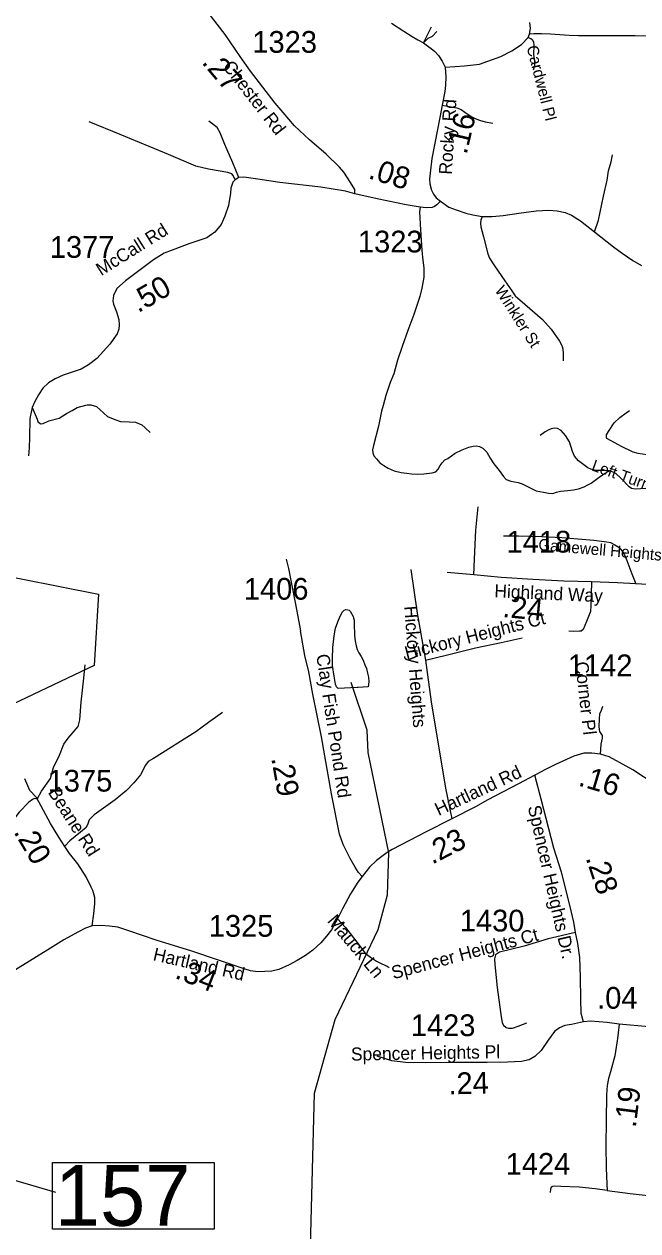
# Model space of a CAD drawing. Extents: x 1159738 to 1321356, y 736314 to 882035.
# Drawn here: x 1223604 to 1227136, y 777846 to 784785 of the extents above; entities that cross this region are included whole.
import ezdxf

# ---------------------------------------------------------------- set-up
doc = ezdxf.new("R2010")
doc.units = 0
for name, color, linetype in [('Exist Boundary Political City Limit New InsideOut', 7, 'Continuous'), ('Exist Hydrographic Creek Single Shore', 7, 'Continuous'), ('Exist Hydrographic Misc Water Feature', 7, 'Continuous'), ('Exist Road Non-System Type 51', 7, 'Continuous'), ('Exist Road Non-System Type 51 Label', 7, 'Continuous'), ('Exist Road Secondary Mileage Hundredths English Label', 7, 'Continuous'), ('Exist Road Secondary Structure Standard Bridge Number Label', 7, 'Continuous'), ('Exist Road Secondary Type 41 Attributed', 7, 'Continuous'), ('Exist Road Secondary Type 51 Attributed', 7, 'Continuous'), ('Exist Road Secondary Type 51 Label', 7, 'Continuous'), ('Exist Road Secondary Type 51 Number Label', 7, 'Continuous')]:
    doc.layers.add(name, color=color, linetype=linetype)

msp = doc.modelspace()

# ---------------------------------------------------------------- linework, layer by layer
at = {"layer": 'Exist Boundary Political City Limit New InsideOut'}
msp.add_lwpolyline([(1223353.7, 781642.3), (1224031.6, 781507.2), (1224008.1, 781097.1), (1223340.4, 780779.9)], dxfattribs=at)
at = {"layer": 'Exist Hydrographic Creek Single Shore'}
msp.add_lwpolyline([(1224472, 776290), (1224764, 776635.4), (1225252, 777754.8), (1225275, 778637.3), (1225394, 779061.7), (1225641, 779578.6), (1225696, 779777.8), (1225702, 780020.5), (1225583.9, 780597.4), (1225579, 780725.5), (1225486, 780999.8)], dxfattribs=at)
at = {"layer": 'Exist Hydrographic Misc Water Feature'}
msp.add_lwpolyline([(1225519.9, 780970.4), (1225411.7, 780965.2), (1225402, 780975.2), (1225396.4, 780990.1), (1225387.6, 781036.2), (1225379, 781096.3), (1225378.1, 781136.5), (1225379.8, 781200.5), (1225387.5, 781268.5), (1225396.7, 781311.8), (1225409.6, 781347.6), (1225422.4, 781381), (1225437.1, 781405.4), (1225445.3, 781415), (1225455.4, 781418.1), (1225467.4, 781417.9), (1225475.4, 781416.1), (1225481.2, 781410.2), (1225498.4, 781379.5), (1225500.2, 781371.3), (1225503.8, 781357.2), (1225503.3, 781337.5), (1225505.6, 781271), (1225508.8, 781237.3), (1225514.2, 781211), (1225521.5, 781188.7), (1225531.1, 781170.4), (1225544.4, 781148), (1225556, 781128.1), (1225565.3, 781101.6), (1225574.8, 781079.3), (1225580.1, 781052.9), (1225585.4, 781029), (1225586.8, 781002.7), (1225584.1, 780974.8), (1225526, 780970.3), (1225519.9, 780970.4)], dxfattribs=at)
at = {"layer": 'Exist Road Non-System Type 51'}
for points in [[(1225901.8, 784678.2), (1225948, 784770.7)], [(1225901.8, 784678.2), (1225929.1, 784705.6), (1225954.3, 784716.1), (1225979.5, 784743.4)], [(1226504, 784708.7), (1226520.6, 784703.1), (1226527.8, 784696.8), (1226534.9, 784684.1), (1226538.1, 784664.2), (1226534.9, 784611.1), (1226540.4, 784573), (1226541.2, 784545.3), (1226534.1, 784520.7)], [(1227208.2, 784716), (1227120.3, 784717.8), (1227023.2, 784717.8), (1226923.5, 784717.8), (1226793.8, 784718.7), (1226739.8, 784719.5), (1226633.7, 784726.8), (1226582.1, 784729.5), (1226537.6, 784730.4), (1226511.3, 784728.6)], [(1226010.3, 784318.9), (1226041.1, 784313.5), (1226093.7, 784304.4), (1226118.2, 784295.3), (1226140, 784279), (1226177.2, 784253.6), (1226198.9, 784243.6), (1226224.3, 784233.6), (1226257, 784223.7), (1226300.5, 784215.5)], [(1224818.2, 783889.8), (1224807.8, 783914.5), (1224799.6, 783924.3), (1224776.8, 783932.5), (1224665.6, 783952.1), (1224592.1, 783968.5), (1224435.3, 784035.5), (1224157.5, 784151.6), (1223979.4, 784223.6)], [(1224839.1, 783903.5), (1224804.8, 783987.3), (1224759.7, 784092.5), (1224732.9, 784161.2), (1224715.7, 784191.3), (1224666.3, 784226.7)], [(1226887, 783590.8), (1226910.1, 783657.6), (1226937.3, 783795.6), (1226959.1, 783887.2), (1226967.2, 783942.2), (1226981.7, 783993.9), (1226989, 784032.9)], [(1225882.8, 783732.3), (1225880, 783706), (1225885.5, 783602.5), (1225893.6, 783482.7), (1225896.4, 783445.5), (1225904.5, 783382.9), (1225904.5, 783329.4), (1225892.7, 783266.7), (1225881, 783218.5), (1225847.4, 783115.9), (1225812.1, 783023.4), (1225779.4, 782930.8), (1225753.1, 782852.7), (1225732.4, 782773.6), (1225709.7, 782723.7), (1225685.2, 782649.3), (1225669.8, 782592.1), (1225660.7, 782560.4), (1225643.5, 782474.2), (1225613.7, 782362), (1225609.2, 782336.6), (1225611, 782320.3), (1225617.3, 782302.2), (1225630.9, 782284.9), (1225651.8, 782263.1), (1225673.5, 782246.8), (1225699.8, 782232.3), (1225734.3, 782216.9), (1225773.3, 782206.9), (1225805, 782202.3), (1225834, 782198.7), (1225864.9, 782197.8), (1225903.9, 782198.7), (1225951.6, 782204.2), (1225973.3, 782210.5), (1225986, 782226), (1225997.8, 782247.7), (1226009.6, 782263.2), (1226025.9, 782279.5), (1226043.1, 782287.7), (1226084, 782317.6), (1226124.8, 782336.7), (1226162.9, 782352.1), (1226188.2, 782357.6), (1226207.3, 782359.4), (1226224.5, 782355.7), (1226244.5, 782347.6), (1226267.1, 782324), (1226286.2, 782289.5), (1226307.9, 782256.8), (1226337.9, 782218.7), (1226362.4, 782184.2), (1226377.8, 782166.1), (1226404.1, 782157.9), (1226447.6, 782149.7), (1226470.8, 782141), (1226511.6, 782120.1), (1226551.5, 782101.9), (1226593.2, 782093.8), (1226621.3, 782088.3), (1226645.8, 782085.6), (1226666.7, 782093.8), (1226691.2, 782100.1), (1226732.9, 782102.8), (1226764.6, 782106.5), (1226794.5, 782113.7), (1226827.2, 782124.6), (1226847.1, 782135.5), (1226866.2, 782146.4), (1226913, 782180.9), (1226943.9, 782200.8), (1226972, 782215.6)], [(1226239.9, 783679.5), (1226232.8, 783657.2), (1226230.9, 783640), (1226231.8, 783620), (1226247.3, 783561.9), (1226272.7, 783464.8), (1226282.6, 783439.4), (1226310.7, 783395), (1226369.7, 783308.7), (1226410.4, 783251.2), (1226430.3, 783222.1), (1226484.7, 783174.9), (1226586.3, 783086), (1226636, 783031.9), (1226684, 782962), (1226696.7, 782940.2), (1226701.3, 782926.6), (1226705.8, 782896.7), (1226706.7, 782849.5)], [(1223650.9, 782580.7), (1223679.5, 782513.3), (1223683.6, 782501), (1223697.8, 782486.7), (1223714.2, 782488.8), (1223746.8, 782503.1), (1223806, 782519.4), (1223848.8, 782546), (1223881.5, 782564.3), (1223910, 782580.7), (1223959, 782595), (1223967.2, 782597), (1223987.6, 782597), (1224020.2, 782586.8), (1224083.5, 782529.6), (1224126.3, 782511.3), (1224159, 782501), (1224207.9, 782499), (1224244.7, 782497), (1224281.4, 782480.6), (1224299.8, 782464.3), (1224330.4, 782437.7)], [(1227278.9, 782122.6), (1227259.6, 782249.3), (1227252.4, 782274.1), (1227242.1, 782286.8), (1227230, 782297.7), (1227214.9, 782303.7), (1227186.5, 782308.6), (1227137.5, 782315.8), (1227108.5, 782324.3), (1227042, 782355.8), (1226957.4, 782402.9), (1226955, 782408.9), (1226955.6, 782423.5), (1226966.5, 782443.4), (1226999.7, 782491.6), (1227031.8, 782522.4), (1227068.6, 782549.7), (1227088.5, 782563.3)], [(1223639.2, 782526.3), (1223636.6, 782513.3), (1223634.6, 782409.2), (1223632.6, 782347.9), (1223628.5, 782303)], [(1227181.5, 782114), (1227119.8, 782111.2), (1227099.8, 782114.9), (1227085.3, 782124), (1227039.1, 782173), (1227009.2, 782200.2), (1226992.8, 782208.3), (1226972, 782215.6), (1226947.5, 782219.2), (1226919.4, 782219.2), (1226893.1, 782219.2), (1226865.9, 782226.5), (1226847.7, 782232.8), (1226824.2, 782251.9), (1226793.3, 782273.7), (1226770.7, 782300.9), (1226758.9, 782328.1), (1226742.6, 782382.6), (1226719.9, 782418.9), (1226694.5, 782448.8), (1226673, 782459.6), (1226656.7, 782462.3), (1226637.6, 782458.7), (1226619.5, 782450.5), (1226603.2, 782441.4), (1226574.2, 782419.6)], [(1226192, 781618.5), (1226195.6, 781709.2), (1226203.7, 781875.3), (1226216.4, 782009.2)], [(1226362.1, 781842.5), (1226448.3, 781843.4), (1226582.5, 781838), (1226697.6, 781833.4), (1226882.6, 781818), (1226957, 781808), (1226977.8, 781803.5), (1227003.2, 781790.8), (1227025.9, 781777.2), (1227045.9, 781754.5), (1227059.5, 781732.7), (1227072.2, 781700), (1227101.2, 781623.8), (1227123.6, 781566.8)], [(1225112.6, 781708.1), (1225124.8, 781654.6), (1225142.1, 781566.6), (1225163.8, 781459.5), (1225185.6, 781347.4), (1225194.7, 781296.6)], [(1225829.9, 781649.2), (1225866.8, 781397.5), (1225914, 781128)], [(1226869.7, 781577.2), (1226867, 781506.4), (1226866.1, 781442), (1226862.5, 781407.5), (1226840.7, 781350.3), (1226821.7, 781304.9), (1226809, 781295), (1226800.8, 781294), (1226768.2, 781293.1), (1226738.2, 781294)], [(1225914, 781128), (1226033.3, 781157.1), (1226202.3, 781198), (1226348.3, 781228.8), (1226470.7, 781256.9)], [(1223680, 780327.8), (1223704.5, 780374.8), (1223755.5, 780446.2), (1223773.9, 780509.5), (1223808.6, 780581), (1223833, 780644.3), (1223857.5, 780679), (1223914.7, 780746.4), (1223924.9, 780785.2), (1223933, 780885.2), (1223945.3, 781007.7), (1223955.4, 781100.8)], [(1225914, 781128), (1225946.8, 780887.6), (1226029.2, 780391.5), (1226064.6, 780215.7)], [(1224745.5, 780827.4), (1224664.8, 780769.7), (1224592.8, 780714.9), (1224347.9, 780562.1), (1224317.6, 780545.5), (1224301.8, 780523.9), (1224274.4, 780467.6), (1224235.5, 780422.9), (1224193.7, 780378.3), (1224128.9, 780323.5), (1224007.8, 780238.4), (1223977.6, 780209.6), (1223970.4, 780186.5), (1223961.7, 780164.9), (1223928.6, 780137.5), (1223866.7, 780088.5), (1223837.8, 780058.2)], [(1226921.5, 780586.8), (1226925.4, 780644.3), (1226931.7, 780679.7), (1226931.7, 780693.9), (1226924.6, 780706.5), (1226916.8, 780717.5), (1226914.4, 780728.5), (1226913.6, 780745.9), (1226915.2, 780789.2), (1226917.5, 780818.3), (1226927, 780840.4), (1226934.9, 780862.4)], [(1223680, 780327.8), (1223663.8, 780332.2), (1223651.5, 780326.1), (1223631.1, 780311.8), (1223576, 780252.6), (1223516.9, 780175), (1223500.5, 780156.6), (1223514.8, 780126), (1223525, 780070.9), (1223514.8, 780023.9), (1223425.6, 779857.9), (1223363.8, 779737.9), (1223345, 779722.9), (1223324.4, 779717.3), (1223313.2, 779722.9), (1223298.2, 779741.6), (1223275.7, 779831.7)], [(1225406.6, 779640.4), (1225453.9, 779590.2), (1225526, 779496.5), (1225566.6, 779443.2), (1225597, 779419.2), (1225632.4, 779396.3), (1225662, 779382), (1225693.2, 779367.6), (1225705, 779360)], [(1226777.3, 779561.2), (1226619, 779525.1), (1226480.8, 779483.6), (1226338.8, 779447.5), (1226316.7, 779433.2), (1226311.3, 779410.9), (1226313.1, 779377.2), (1226326.9, 779245.3), (1226348, 779090.7), (1226355.8, 779042.8), (1226363, 779027.7), (1226378.1, 779015.7), (1226391.9, 779011.5), (1226414.2, 779012.1), (1226446.6, 779022.3), (1226497.2, 779041.6)], [(1226959.4, 778078.5), (1226890.5, 778086.3), (1226797.1, 778096), (1226693, 778101.1), (1226656, 778101.7), (1226644.6, 778101.1), (1226637.7, 778096.6), (1226633.2, 778085.8), (1226630.3, 778065.3)], [(1226959.4, 778078.5), (1227091.3, 778060.1), (1227228.9, 778045.2), (1227332.5, 778039.5), (1227371.7, 778029.9)]]:
    msp.add_lwpolyline(points, dxfattribs=at)
at = {"layer": 'Exist Road Secondary Structure Standard Bridge Number Label'}
msp.add_line((1222322, 778494.1), (1223785.5, 778067.2), dxfattribs=at)
msp.add_lwpolyline([(1223768.2, 778238.9), (1224697.2, 778238.9), (1224697.2, 777854.8), (1223768.2, 777854.8)], close=True, dxfattribs=at)
at = {"layer": 'Exist Road Secondary Type 41 Attributed'}
for points in [[(1225550, 779882.9), (1225527.9, 779907.1), (1225508.4, 779936.6), (1225479.6, 779986.9), (1225439.4, 780068.3), (1225418.3, 780127), (1225373.8, 780358.6), (1225315.3, 780686.5), (1225265, 780931.3), (1225242.7, 781061.4), (1225219.3, 781155.3), (1225194.7, 781296.6)], [(1226822.7, 779047.4), (1226809.2, 779094.7), (1226808.2, 779178.7), (1226805.3, 779305.1), (1226801.3, 779416.9), (1226790.6, 779497.3), (1226777.3, 779561.2), (1226768, 779620.4), (1226743.5, 779719.5), (1226695.5, 779907.8), (1226653.2, 780046.8), (1226579.8, 780328.7), (1226543.5, 780467.2)]]:
    msp.add_lwpolyline(points, dxfattribs=at)
at = {"layer": 'Exist Road Secondary Type 51 Attributed'}
for points in [[(1225507.8, 783810), (1225506.7, 783834.8), (1225482.9, 783873.8), (1225443, 783934.7), (1225418.6, 783963.7), (1225341.6, 784037.9), (1225246.6, 784120.6), (1225159.1, 784201), (1225095, 784276.6), (1225049.4, 784330.8), (1224907.2, 784514.1), (1224847.3, 784599.7), (1224761.8, 784726.6), (1224682, 784826.5), (1224645.7, 784884.1)], [(1225718.5, 784791.5), (1225788.8, 784744.9), (1225836.3, 784714.5), (1225869.6, 784694.5), (1225901.8, 784678.2), (1225932.1, 784654.9), (1225947.3, 784645.4), (1225968.2, 784628.3), (1225989.1, 784605.5), (1226009.2, 784572.3), (1226027.1, 784537.5)], [(1226027.1, 784537.5), (1226139, 784545.1), (1226224.5, 784555.3), (1226346.8, 784599.6), (1226410.1, 784631.3), (1226467.1, 784667.5), (1226504, 784708.7), (1226511.3, 784728.6), (1226517.1, 784760.5), (1226514.6, 784794.7)], [(1226027.1, 784537.5), (1226030.9, 784483.3), (1226028.3, 784435.1), (1226025.2, 784397.7), (1226010.3, 784318.9), (1225996.7, 784249.1), (1225967.6, 784101.2), (1225950.5, 784013), (1225940.3, 783928.1), (1225937.2, 783893.2), (1225939.7, 783866.6), (1225949.2, 783831.1), (1225960, 783807), (1225975.2, 783786.7), (1225999.3, 783766.5)], [(1225507.8, 783810), (1225453.5, 783824.3), (1225312.3, 783846.9), (1225075.7, 783874), (1224948.1, 783893.2), (1224869, 783904.5), (1224839.1, 783903.5), (1224818.2, 783889.8), (1224805.8, 783876.3), (1224793.3, 783842.4), (1224792.2, 783814.1), (1224779.8, 783742.9), (1224759.5, 783681.9), (1224737.1, 783632.5), (1224702.1, 783589.6), (1224654.6, 783556.8), (1224558.6, 783524), (1224410.7, 783467.5), (1224348.8, 783430.6), (1224188.4, 783309.7), (1224137.5, 783264.5), (1224118.4, 783224.3), (1224115, 783193.7), (1224118.4, 783174.5), (1224136.5, 783130.5), (1224150, 783087.5), (1224151.1, 783057), (1224148.9, 783031), (1224139.9, 783003.9), (1224098.3, 782945.5), (1224022.7, 782863), (1223975.2, 782825.7), (1223932.3, 782801.9), (1223829.5, 782765.8), (1223783.2, 782745.4), (1223744.8, 782721.7), (1223712.1, 782692.3), (1223686.1, 782653.9), (1223663.2, 782611.3), (1223650.9, 782580.7), (1223639.2, 782526.3)], [(1225999.3, 783766.5), (1225978.8, 783745.4), (1225964.9, 783735.9), (1225951.6, 783730.2), (1225918, 783728.3), (1225882.8, 783732.3), (1225801.8, 783745.9), (1225635.8, 783780.2), (1225507.8, 783810)], [(1225999.3, 783766.5), (1226048, 783733.2), (1226089.8, 783717), (1226145.2, 783698.2), (1226187, 783688), (1226239.9, 783679.5), (1226297.9, 783678.6), (1226361, 783685.4), (1226450.6, 783697.4), (1226551.3, 783711.9), (1226622.9, 783715.3), (1226672.1, 783711.2), (1226717.3, 783701.8), (1226754.8, 783687.2), (1226806, 783654.8), (1226887, 783590.8), (1226995.9, 783504), (1227046.3, 783468.2), (1227106, 783425.5), (1227156.3, 783397.3)], [(1227308.7, 781549), (1227219.7, 781561.4), (1227123.6, 781566.8), (1227018.1, 781572.7), (1226869.7, 781577.2), (1226710, 781582.8), (1226530.8, 781590.7), (1226349.5, 781603.1), (1226192, 781618.5), (1226038.8, 781631)], [(1227235.1, 780411.9), (1227106, 780497.3), (1227030.8, 780538.5), (1226969.9, 780572.5), (1226921.5, 780586.8), (1226871.4, 780592.2), (1226824.8, 780592.2), (1226767.3, 780575.4), (1226661.8, 780527.7), (1226604.8, 780498), (1226543.5, 780467.2)], [(1226543.5, 780467.2), (1226448.7, 780416.2), (1226269.4, 780322.9), (1226204.9, 780286.6), (1226064.6, 780215.7), (1225918.5, 780140.7), (1225722.7, 780038.6), (1225693, 780021.4), (1225662, 779999), (1225631.8, 779976.2), (1225592.3, 779937.3), (1225550, 779882.9)], [(1223996.3, 779600.3), (1224005.2, 779668.8), (1224010.5, 779727.8), (1224010.5, 779762.6), (1223998.9, 779802.6), (1223990.4, 779822.6), (1223960.4, 779880.7), (1223912.9, 779955.7), (1223865.8, 780016.4), (1223837.6, 780056.3), (1223803.6, 780109), (1223755.6, 780187.6), (1223676.2, 780337.6), (1223636.1, 780377.6), (1223607.9, 780444.7)], [(1225550, 779882.9), (1225524.6, 779851.5), (1225483, 779783.7), (1225436, 779697.8), (1225406.6, 779640.4), (1225372.4, 779577.3), (1225344.9, 779541.1), (1225312.1, 779501.5), (1225264.6, 779459.4), (1225223, 779428.6), (1225175.4, 779400.4), (1225128.4, 779374.9), (1225069.6, 779348.9), (1225028.7, 779338.2), (1224948.2, 779335.6), (1224906.2, 779341.8), (1224875.8, 779350.7), (1224569.4, 779454.5), (1224363.8, 779517.9), (1224205.8, 779571.8), (1224142.8, 779591.5), (1224096.1, 779597.7), (1224044.3, 779601.7), (1223996.3, 779600.3)], [(1223996.3, 779600.3), (1223957.8, 779585.6), (1223912.5, 779563.4), (1223833.5, 779519.2), (1223740.7, 779462.3), (1223569, 779356.9), (1222832.5, 778890.2), (1222414.8, 778632.8), (1222153.6, 778478)], [(1226822.7, 779047.4), (1226754.4, 779033), (1226715.8, 779025.8), (1226684.4, 779013.4), (1226657, 778991.8), (1226619.3, 778942.4), (1226578.8, 778883.5), (1226542.2, 778847.6), (1226510.2, 778828.6), (1226466.4, 778818.8), (1226385, 778816.2), (1226268, 778812.9), (1226087.2, 778812.9), (1225915.4, 778811), (1225799.1, 778814.2), (1225720.7, 778823.4), (1225636.4, 778849.5)], [(1227029, 779035.1), (1226960.1, 779044.2), (1226862.7, 779051), (1226822.7, 779047.4)], [(1227029, 779035.1), (1227018.9, 778952.7), (1227003.9, 778852.2), (1226978.6, 778760.1), (1226966, 778721.1), (1226959.4, 778682), (1226955.2, 778627.2), (1226953.4, 778480), (1226952.2, 778334.5), (1226954, 778208.9), (1226957, 778114.1), (1226959.4, 778078.5)], [(1227503, 779005), (1227471.8, 779004.9), (1227387, 779009.2), (1227198, 779019.4), (1227029, 779035.1)]]:
    msp.add_lwpolyline(points, dxfattribs=at)

# ---------------------------------------------------------------- texts
at = {"layer": 'Exist Road Non-System Type 51 Label'}
for s, height, rotation, p in [('Cardwell Pl', 65.617, 284.30807, (1226495.1, 784654.1)), ('Winkler St', 65.62, 302.52815, (1226310.2, 783255)), ('Left Turn Ln', 65.617, 340.40491, (1226864.6, 782220.6)), ('Gamewell Heights', 65.617, 355.01785, (1226561.2, 781761.2)), ('Hickory Heights', 75, 274.35744, (1225790.8, 781437.3)), ('Hickory Heights Ct', 75, 14.38212, (1225805.1, 781131.1)), ('Corner Pl', 75, 276.44592, (1226774.9, 781115.2)), ('Mauck Ln', 75, 310.074, (1225344.4, 779625.7)), ('Spencer Heights Ct', 75, 14.97591, (1225729.2, 779292))]:
    msp.add_text(s, height=height, rotation=rotation, dxfattribs=at).set_placement(p)
at = {"layer": 'Exist Road Secondary Mileage Hundredths English Label'}
for s, rotation, p in [('.27', 310.34028, (1224622.4, 784563.5)), ('.16', 76.51974, (1226149.9, 784031.8)), ('.08', 342.7616, (1225579.3, 783900.4)), ('.50', 29.95024, (1224260, 783122.4)), ('.24', 354.41162, (1226354.1, 781376.4)), ('.29', 280.04151, (1225025.7, 780563.8)), ('.16', 343.48624, (1226787.9, 780407.8)), ('.20', 300.49427, (1223541.3, 780139.9)), ('.23', 27.2222, (1225951.9, 779950.4)), ('.28', 288.46888, (1226834.3, 779989.9)), ('.34', 338.55721, (1224465.8, 779301.6)), ('.24', 1.29718, (1226047.2, 778630.3)), ('.19', 82.91872, (1227123.5, 778435.8))]:
    msp.add_text(s, height=125, rotation=rotation, dxfattribs=at).set_placement(p)
msp.add_text('.04', height=125, dxfattribs=at).set_placement((1226901.5, 779123.1))
at = {"layer": 'Exist Road Secondary Structure Standard Bridge Number Label'}
msp.add_text('157', height=350, dxfattribs=at).set_placement((1223780.8, 777874.6))
at = {"layer": 'Exist Road Secondary Type 51 Label'}
for s, rotation, p in [('Chester Rd', 308.01929, (1224743.6, 784539.9)), ('Rocky Rd', 86.37999, (1226065.1, 783918.2)), ('McCall Rd', 32.1052, (1224047.6, 783335.1)), ('Highland Way', 357.40478, (1226308.8, 781489)), ('Clay Fish Pond Rd', 278.69098, (1225284.8, 781157.3)), ('Hartland Rd', 25.06711, (1225989.2, 780231.1)), ('Beane Rd', 302.73739, (1223738.7, 780367.3)), ('Spencer Heights Dr.', 282.81937, (1226502.1, 780284)), ('Hartland Rd', 347.12753, (1224341.6, 779402.6)), ('Spencer Heights Pl', 0.93977, (1225485.4, 778824.5))]:
    msp.add_text(s, height=75, rotation=rotation, dxfattribs=at).set_placement(p)
at = {"layer": 'Exist Road Secondary Type 51 Number Label'}
for s, p in [('1323', (1224917.5, 784620.8)), ('1323', (1225525, 783472.5)), ('1377', (1223751.8, 783441.4)), ('1418', (1226380.1, 781746.4)), ('1406', (1224868.6, 781475.5)), ('1142', (1226732.9, 781035.3)), ('1375', (1223739.7, 780371.8)), ('1325', (1224666.7, 779537)), ('1430', (1226111.2, 779567.3)), ('1423', (1225829.1, 778965.4)), ('1424', (1226375.3, 778168.1))]:
    msp.add_text(s, height=125, dxfattribs=at).set_placement(p)

doc.saveas('drawing.dxf')
